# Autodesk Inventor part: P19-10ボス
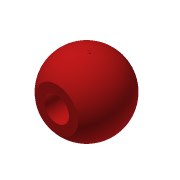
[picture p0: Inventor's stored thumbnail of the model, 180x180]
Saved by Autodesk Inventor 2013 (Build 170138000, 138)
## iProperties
Created: 2008-07
Part Number: P19-10ボス
Document SubType Name: Modeling
Designer: y-shimohigashi
Density: 1 g/cm^3
Stock Number: P19-10ボス
Material: 一般
Author: y-shimohigashi
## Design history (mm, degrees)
sketch "スケッチ1"
  geometry: L1 (0, 12)-(0, 3.253); L2 (0, 3.253)-(4, 3.253); L3 (4, 3.253)-(4, -9.747); L4 (4, -9.747)-(7, -9.747); A1 r 12 centre (0, 0) between (7, -9.747) and (0, 12); 1 further point
  constraints: 8 end point, 2 parallel, 2 point on circle, 1 centre point, 1 coincident, 1 perpendicular, 1 point on line, 1 vertical
  dimensions: "d0" = 4 distance of L1.end L2.end; "d1" = 3 distance of L3.end L4.end; "d2" = 13 distance of L2.end L3.end; "d3" = 12 radius of A1
revolve "回転1" sketch "スケッチ1" stored, may be unused: angle "d4" = 90 deg
node "ソリッド1"
node "ソリッド ボディ"
node "サーフェス ボディ"
